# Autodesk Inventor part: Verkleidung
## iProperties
Created: 2006-10
Part Number: Verkleidung
Document SubType Name: Sheet Metal
Designer: ST03
Author: ST03
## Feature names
1. Grobblech1
2. Grobblech2
3. Biegung1
4. Grobblech3
5. Biegung2
6. Grobblech4
7. Biegung3
8. Grobblech5
9. Biegung4
10. Ausklinkung1
